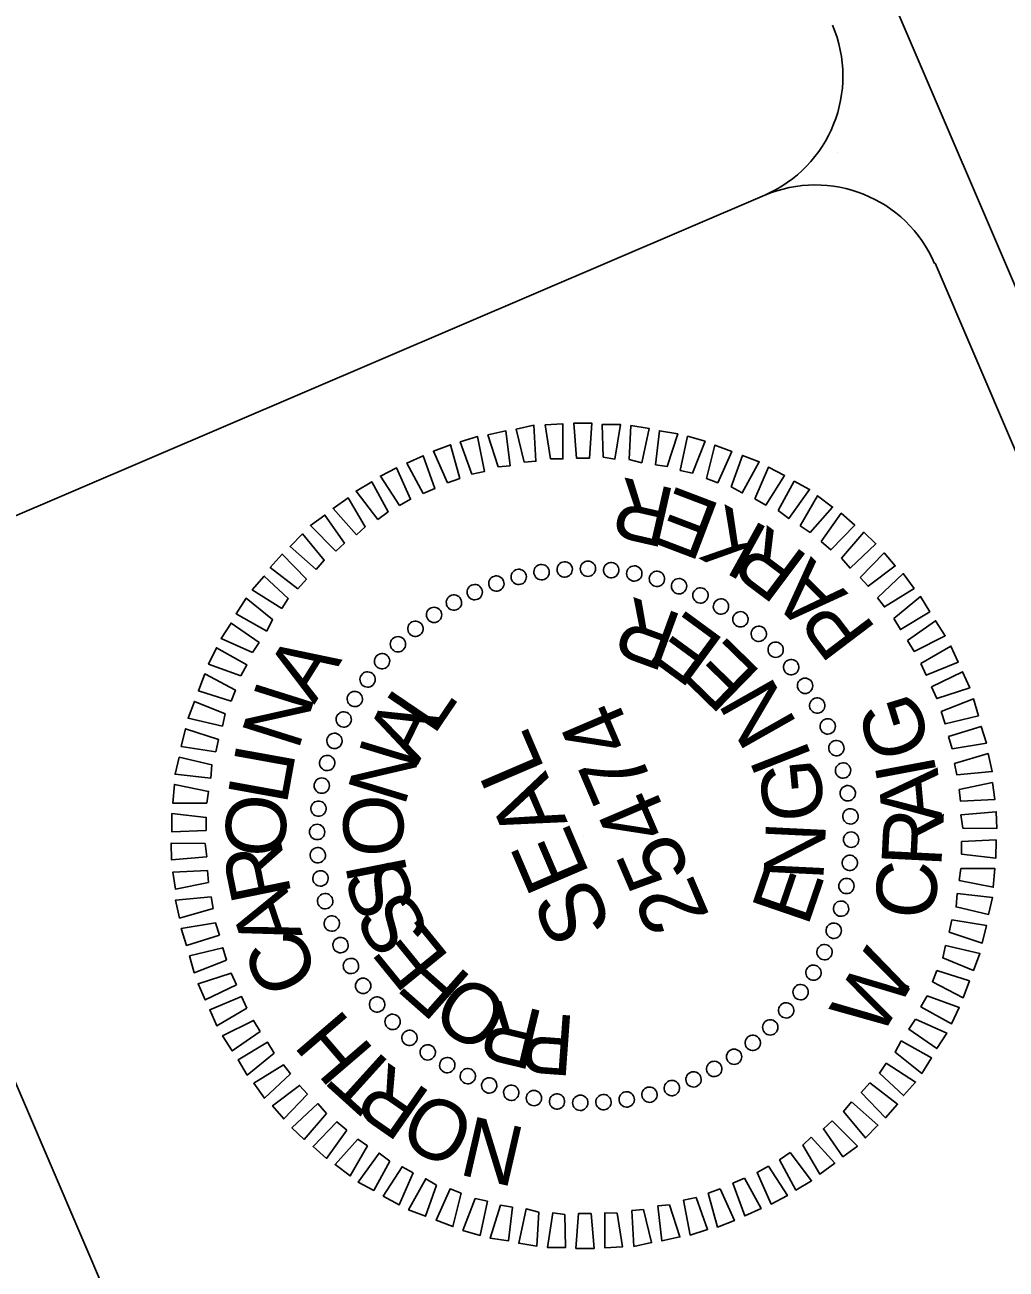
# Model space of a CAD drawing. Extents: x 1550250 to 1553210, y 808906 to 812497.
# Drawn here: x 1552075.2 to 1552205.6, y 811622.3 to 811787.7 of the extents above; entities that cross this region are included whole.
import ezdxf

# ---------------------------------------------------------------- set-up
doc = ezdxf.new("R2010")
doc.units = 0
doc.layers.add('Old_Level_50', color=7, linetype='Continuous')
doc.layers.add('Sheet_Title_CELL', color=7, linetype='Continuous')

msp = doc.modelspace()

# ---------------------------------------------------------------- linework, layer by layer
at = {"layer": 'Old_Level_50'}
for p, q in [((1552183.22, 811770.69), (1552183.22, 811770.69)), ((1552149.96, 811715.41), (1552149.96, 811715.41)), ((1552140.76, 811714.31), (1552140.76, 811714.31)), ((1552143.8, 811714.98), (1552143.8, 811714.98)), ((1552146.89, 811715.35), (1552146.89, 811715.35)), ((1552153.06, 811715.25), (1552153.06, 811715.25)), ((1552156.15, 811714.78), (1552156.15, 811714.78)), ((1552159.16, 811714.11), (1552159.16, 811714.11)), ((1552134.91, 811712.31), (1552134.91, 811712.31)), ((1552137.81, 811713.45), (1552137.81, 811713.45)), ((1552162.1, 811713.1), (1552162.1, 811713.1)), ((1552132.13, 811710.9), (1552132.13, 811710.9)), ((1552164.96, 811711.91), (1552164.96, 811711.91)), ((1552129.53, 811709.27), (1552129.53, 811709.27)), ((1552167.65, 811710.4), (1552167.65, 811710.4)), ((1552127.01, 811707.44), (1552127.01, 811707.44)), ((1552170.27, 811708.71), (1552170.27, 811708.71)), ((1552172.69, 811706.77), (1552172.69, 811706.77)), ((1552124.68, 811705.38), (1552124.68, 811705.38)), ((1552174.95, 811704.68), (1552174.95, 811704.68)), ((1552122.59, 811703.13), (1552122.59, 811703.13)), ((1552177.01, 811702.34), (1552177.01, 811702.34)), ((1552120.65, 811700.71), (1552120.65, 811700.71)), ((1552178.84, 811699.83), (1552178.84, 811699.83)), ((1552118.96, 811698.09), (1552118.96, 811698.09)), ((1552180.47, 811697.23), (1552180.47, 811697.23)), ((1552117.45, 811695.39), (1552117.45, 811695.39)), ((1552181.87, 811694.44), (1552181.87, 811694.44)), ((1552116.25, 811692.53), (1552116.25, 811692.53)), ((1552183.02, 811691.55), (1552183.02, 811691.55)), ((1552115.25, 811689.59), (1552115.25, 811689.59)), ((1552183.88, 811688.6), (1552183.88, 811688.6)), ((1552114.58, 811686.58), (1552114.58, 811686.58)), ((1552184.54, 811685.56), (1552184.54, 811685.56)), ((1552114.1, 811683.49), (1552114.1, 811683.49)), ((1552184.92, 811682.47), (1552184.92, 811682.47)), ((1552113.94, 811680.4), (1552113.94, 811680.4)), ((1552149.46, 811679.9), (1552149.46, 811679.9)), ((1552184.98, 811679.39), (1552184.98, 811679.39)), ((1552114.01, 811677.32), (1552114.01, 811677.32)), ((1552184.82, 811676.3), (1552184.82, 811676.3)), ((1552114.38, 811674.23), (1552114.38, 811674.23)), ((1552184.34, 811673.21), (1552184.34, 811673.21)), ((1552115.05, 811671.2), (1552115.05, 811671.2)), ((1552183.68, 811670.2), (1552183.68, 811670.2)), ((1552115.91, 811668.25), (1552115.91, 811668.25)), ((1552182.67, 811667.26), (1552182.67, 811667.26)), ((1552117.05, 811665.35), (1552117.05, 811665.35)), ((1552181.47, 811664.4), (1552181.47, 811664.4)), ((1552118.46, 811662.57), (1552118.46, 811662.57)), ((1552179.97, 811661.71), (1552179.97, 811661.71)), ((1552120.09, 811659.96), (1552120.09, 811659.96)), ((1552178.27, 811659.09), (1552178.27, 811659.09)), ((1552121.92, 811657.45), (1552121.92, 811657.45)), ((1552176.34, 811656.66), (1552176.34, 811656.66)), ((1552123.97, 811655.11), (1552123.97, 811655.11)), ((1552174.25, 811654.41), (1552174.25, 811654.41)), ((1552126.23, 811653.02), (1552126.23, 811653.02)), ((1552128.65, 811651.08), (1552128.65, 811651.08)), ((1552171.91, 811652.35), (1552171.91, 811652.35)), ((1552131.27, 811649.39), (1552131.27, 811649.39)), ((1552169.4, 811650.52), (1552169.4, 811650.52)), ((1552133.97, 811647.88), (1552133.97, 811647.88)), ((1552166.79, 811648.89), (1552166.79, 811648.89)), ((1552136.83, 811646.69), (1552136.83, 811646.69)), ((1552161.11, 811646.34), (1552161.11, 811646.34)), ((1552164.01, 811647.48), (1552164.01, 811647.48)), ((1552139.77, 811645.68), (1552139.77, 811645.68)), ((1552142.78, 811645.01), (1552142.78, 811645.01)), ((1552145.86, 811644.54), (1552145.86, 811644.54)), ((1552148.96, 811644.38), (1552148.96, 811644.38)), ((1552152.04, 811644.44), (1552152.04, 811644.44)), ((1552155.12, 811644.82), (1552155.12, 811644.82)), ((1552158.16, 811645.48), (1552158.16, 811645.48))]:
    msp.add_line(p, q, dxfattribs=at)
for points in [[(1552138.08, 811728.93), (1552136.71, 811733.2), (1552139.1, 811733.73), (1552139.64, 811729.09)], [(1552141.53, 811729.55), (1552140.48, 811733.96), (1552142.81, 811734.47), (1552143.09, 811729.7)], [(1552145.03, 811730.03), (1552144.33, 811734.53), (1552146.68, 811734.65), (1552146.68, 811730)], [(1552148.49, 811730.11), (1552148.11, 811734.75), (1552150.52, 811734.75), (1552150.2, 811730.1)], [(1552152.01, 811730.22), (1552151.91, 811734.59), (1552154.31, 811734.59), (1552153.58, 811729.99)], [(1552155.48, 811729.91), (1552155.7, 811734.43), (1552158.12, 811734.05), (1552157.14, 811729.5)], [(1552158.97, 811729.23), (1552159.5, 811733.74), (1552161.93, 811733.35), (1552160.54, 811729.01)], [(1552134.55, 811727.97), (1552133.02, 811732.25), (1552135.33, 811732.97), (1552136.25, 811728.34)], [(1552162.26, 811728.46), (1552163.24, 811733.01), (1552165.56, 811732.34), (1552163.89, 811728.11)], [(1552128.11, 811725.39), (1552125.91, 811729.44), (1552128.1, 811730.42), (1552129.66, 811726.08)], [(1552131.34, 811726.84), (1552129.46, 811731.03), (1552131.71, 811731.89), (1552132.95, 811727.4)], [(1552165.76, 811727.39), (1552166.87, 811731.85), (1552169.11, 811730.99), (1552167.26, 811726.83)], [(1552169.04, 811726.31), (1552170.52, 811730.46), (1552172.76, 811729.6), (1552170.5, 811725.49)], [(1552124.94, 811723.81), (1552122.41, 811727.72), (1552124.55, 811728.83), (1552126.43, 811724.63)], [(1552172.18, 811724.69), (1552174, 811728.92), (1552176.14, 811727.78), (1552173.63, 811723.87)], [(1552122.05, 811721.97), (1552119.19, 811725.73), (1552121.27, 811726.97), (1552123.45, 811722.98)], [(1552175.28, 811723.13), (1552177.41, 811727.03), (1552179.45, 811725.94), (1552176.69, 811722.06)], [(1552119.24, 811719.93), (1552116.12, 811723.42), (1552118.11, 811724.85), (1552120.39, 811720.99)], [(1552178.2, 811721.11), (1552180.52, 811725.1), (1552182.52, 811723.59), (1552179.53, 811720.23)], [(1552116.49, 811717.76), (1552113.11, 811721.14), (1552115.04, 811722.54), (1552117.64, 811718.82)], [(1552181, 811719.03), (1552183.66, 811722.78), (1552185.46, 811721.19), (1552182.28, 811717.9)], [(1552113.88, 811715.28), (1552110.4, 811718.37), (1552112.05, 811720.04), (1552114.95, 811716.53)], [(1552183.7, 811716.83), (1552186.66, 811720.25), (1552188.27, 811718.73), (1552184.84, 811715.48)], [(1552111.46, 811712.72), (1552107.78, 811715.56), (1552109.37, 811717.36), (1552112.59, 811714)], [(1552186.18, 811714.22), (1552189.36, 811717.51), (1552190.84, 811715.77), (1552187.24, 811713.07)], [(1552109.29, 811710.11), (1552105.37, 811712.62), (1552106.97, 811714.42), (1552110.17, 811711.44)], [(1552188.48, 811711.53), (1552191.91, 811714.77), (1552193.34, 811712.78), (1552189.41, 811710.32)], [(1552107.3, 811707.12), (1552103.24, 811709.42), (1552104.57, 811711.48), (1552108.09, 811708.64)], [(1552190.64, 811708.78), (1552194.22, 811711.7), (1552195.43, 811709.68), (1552191.53, 811707.31)], [(1552105.4, 811704.26), (1552101.24, 811706.11), (1552102.56, 811708.18), (1552106.28, 811705.58)], [(1552192.49, 811705.88), (1552196.21, 811708.48), (1552197.49, 811706.49), (1552193.38, 811704.42)], [(1552103.85, 811701.15), (1552099.58, 811702.73), (1552100.62, 811704.9), (1552104.67, 811702.61)], [(1552194.26, 811702.8), (1552198.25, 811705.13), (1552199.21, 811703), (1552194.96, 811701.25)], [(1552102.57, 811697.79), (1552098.22, 811699.17), (1552099.08, 811701.42), (1552103.14, 811699.28)], [(1552195.65, 811699.7), (1552199.79, 811701.71), (1552200.74, 811699.58), (1552196.35, 811698.15)], [(1552101.42, 811694.48), (1552096.84, 811695.52), (1552097.69, 811697.77), (1552101.77, 811696.11)], [(1552196.97, 811696.41), (1552201.25, 811698.1), (1552201.89, 811695.83), (1552197.47, 811694.77)], [(1552100.55, 811691.06), (1552095.95, 811691.79), (1552096.52, 811694.14), (1552100.9, 811692.69)], [(1552197.91, 811693.11), (1552202.27, 811694.45), (1552202.97, 811692.2), (1552198.41, 811691.47)], [(1552198.74, 811689.53), (1552203.2, 811690.83), (1552203.73, 811688.43), (1552199.03, 811688.03)], [(1552099.86, 811687.57), (1552095.13, 811688.09), (1552095.67, 811690.35), (1552100, 811689.34)], [(1552099.34, 811684.24), (1552094.84, 811684.24), (1552095.04, 811686.73), (1552099.57, 811685.81)], [(1552199.36, 811686.08), (1552203.77, 811686.97), (1552204.08, 811684.71), (1552199.51, 811684.52)], [(1552099.25, 811680.63), (1552094.69, 811680.44), (1552094.69, 811682.85), (1552099.26, 811682.34)], [(1552199.56, 811682.68), (1552204.27, 811683.09), (1552204.34, 811680.87), (1552199.81, 811680.93)], [(1552199.67, 811679.16), (1552204.24, 811679.35), (1552204.23, 811676.94), (1552199.66, 811677.45)], [(1552099.36, 811677.11), (1552094.66, 811676.7), (1552094.59, 811678.92), (1552099.12, 811678.86)], [(1552099.57, 811673.71), (1552095.16, 811672.82), (1552094.84, 811675.08), (1552099.41, 811675.27)], [(1552199.58, 811675.55), (1552204.08, 811675.56), (1552203.88, 811673.06), (1552199.36, 811673.98)], [(1552100.18, 811670.26), (1552095.73, 811668.96), (1552095.19, 811671.36), (1552099.9, 811671.77)], [(1552199.06, 811672.22), (1552203.79, 811671.7), (1552203.26, 811669.45), (1552198.93, 811670.45)], [(1552101.02, 811666.68), (1552096.65, 811665.34), (1552095.95, 811667.59), (1552100.51, 811668.32)], [(1552198.38, 811668.73), (1552202.97, 811668), (1552202.4, 811665.65), (1552198.03, 811667.1)], [(1552101.96, 811663.38), (1552097.67, 811661.69), (1552097.04, 811663.97), (1552101.45, 811665.02)], [(1552197.51, 811665.31), (1552202.09, 811664.27), (1552201.23, 811662.02), (1552197.16, 811663.68)], [(1552103.28, 811660.09), (1552099.14, 811658.08), (1552098.18, 811660.21), (1552102.58, 811661.64)], [(1552196.36, 811662), (1552200.7, 811660.62), (1552199.85, 811658.37), (1552195.79, 811660.51)], [(1552104.67, 811657), (1552100.67, 811654.66), (1552099.72, 811656.79), (1552103.97, 811658.54)], [(1552195.07, 811658.64), (1552199.35, 811657.06), (1552198.31, 811654.89), (1552194.25, 811657.18)], [(1552106.44, 811653.91), (1552102.72, 811651.31), (1552101.44, 811653.3), (1552105.55, 811655.37)], [(1552193.52, 811655.53), (1552197.69, 811653.68), (1552196.37, 811651.61), (1552192.64, 811654.21)], [(1552191.63, 811652.67), (1552195.68, 811650.38), (1552194.36, 811648.31), (1552190.83, 811651.15)], [(1552108.28, 811651.02), (1552104.71, 811648.09), (1552103.49, 811650.11), (1552107.39, 811652.48)], [(1552110.45, 811648.27), (1552107.02, 811645.02), (1552105.58, 811647.01), (1552109.52, 811649.48)], [(1552189.63, 811649.68), (1552193.55, 811647.17), (1552191.95, 811645.37), (1552188.75, 811648.35)], [(1552112.74, 811645.57), (1552109.56, 811642.28), (1552108.08, 811644.02), (1552111.68, 811646.72)], [(1552187.47, 811647.08), (1552191.15, 811644.23), (1552189.55, 811642.43), (1552186.33, 811645.79)], [(1552115.23, 811642.97), (1552112.27, 811639.54), (1552110.65, 811641.07), (1552114.08, 811644.31)], [(1552185.05, 811644.52), (1552188.53, 811641.43), (1552186.87, 811639.75), (1552183.98, 811643.26)], [(1552117.93, 811640.76), (1552115.27, 811637.01), (1552113.47, 811638.6), (1552116.64, 811641.89)], [(1552182.44, 811642.03), (1552185.81, 811638.66), (1552183.89, 811637.25), (1552181.29, 811640.97)], [(1552120.72, 811638.68), (1552118.4, 811634.69), (1552116.4, 811636.2), (1552119.4, 811639.56)], [(1552179.69, 811639.86), (1552182.8, 811636.37), (1552180.81, 811634.94), (1552178.54, 811638.8)], [(1552123.65, 811636.66), (1552121.52, 811632.76), (1552119.47, 811633.86), (1552122.23, 811637.73)], [(1552176.88, 811637.82), (1552179.73, 811634.06), (1552177.65, 811632.82), (1552175.47, 811636.81)], [(1552126.75, 811635.1), (1552124.92, 811630.87), (1552122.79, 811632.01), (1552125.3, 811635.92)], [(1552170.81, 811634.4), (1552173.02, 811630.35), (1552170.83, 811629.37), (1552169.26, 811633.71)], [(1552173.98, 811635.98), (1552176.51, 811632.08), (1552174.37, 811630.96), (1552172.49, 811635.16)], [(1552129.88, 811633.48), (1552128.41, 811629.33), (1552126.16, 811630.19), (1552128.43, 811634.31)], [(1552133.16, 811632.4), (1552132.06, 811627.95), (1552129.81, 811628.8), (1552131.67, 811632.97)], [(1552167.59, 811632.96), (1552169.47, 811628.76), (1552167.22, 811627.9), (1552165.98, 811632.39)], [(1552136.66, 811631.33), (1552135.68, 811626.78), (1552133.37, 811627.45), (1552135.03, 811631.69)], [(1552164.37, 811631.82), (1552165.9, 811627.55), (1552163.59, 811626.82), (1552162.68, 811631.45)], [(1552139.96, 811630.56), (1552139.42, 811626.05), (1552137, 811626.44), (1552138.38, 811630.79)], [(1552143.45, 811629.88), (1552143.22, 811625.36), (1552140.8, 811625.74), (1552141.78, 811630.3)], [(1552146.92, 811629.57), (1552147.02, 811625.2), (1552144.61, 811625.2), (1552145.34, 811629.8)], [(1552150.44, 811629.68), (1552150.81, 811625.04), (1552148.41, 811625.05), (1552148.73, 811629.69)], [(1552153.89, 811629.76), (1552154.59, 811625.26), (1552152.24, 811625.14), (1552152.25, 811629.8)], [(1552157.4, 811630.24), (1552158.45, 811625.83), (1552156.12, 811625.33), (1552155.84, 811630.09)], [(1552160.84, 811630.86), (1552162.22, 811626.59), (1552159.82, 811626.06), (1552159.29, 811630.7)]]:
    msp.add_lwpolyline(points, close=True, dxfattribs=at)
for centre, major_axis in [((1552140.8, 811714.32), (-0.25, 0.988)), ((1552143.83, 811714.95), (-0.16, 1.01)), ((1552146.91, 811715.31), (-0.07, 1.02)), ((1552150, 811715.4), (0.01, 1.02)), ((1552153.09, 811715.22), (0.1, 1.01)), ((1552156.16, 811714.77), (0.19, 1)), ((1552137.83, 811713.43), (-0.335, 0.963)), ((1552159.17, 811714.05), (0.278, 0.98)), ((1552162.11, 811713.08), (0.362, 0.952)), ((1552134.95, 811712.29), (-0.417, 0.93)), ((1552164.95, 811711.85), (0.444, 0.917)), ((1552129.55, 811709.27), (-0.572, 0.843)), ((1552132.19, 811710.9), (-0.497, 0.89)), ((1552167.68, 811710.38), (0.522, 0.875)), ((1552170.27, 811708.68), (0.596, 0.826)), ((1552127.07, 811707.42), (-0.644, 0.79)), ((1552172.7, 811706.76), (0.666, 0.771)), ((1552124.75, 811705.36), (-0.71, 0.731)), ((1552174.95, 811704.64), (0.731, 0.71)), ((1552122.63, 811703.11), (-0.771, 0.666)), ((1552177.01, 811702.32), (0.79, 0.644)), ((1552120.71, 811700.68), (-0.826, 0.596)), ((1552178.86, 811699.84), (0.843, 0.572)), ((1552119.01, 811698.09), (-0.875, 0.522)), ((1552180.48, 811697.21), (0.89, 0.497)), ((1552117.54, 811695.37), (-0.917, 0.444)), ((1552181.87, 811694.44), (0.93, 0.417)), ((1552116.31, 811692.52), (-0.952, 0.362)), ((1552183.02, 811691.56), (0.963, 0.335)), ((1552115.34, 811689.58), (-0.98, 0.278)), ((1552183.91, 811688.59), (0.988, 0.25)), ((1552114.62, 811686.57), (-1, 0.19)), ((1552184.53, 811685.56), (1.01, 0.16)), ((1552114.18, 811683.51), (-1.01, 0.1)), ((1552184.89, 811682.49), (1.02, 0.07)), ((1552114, 811680.41), (-1.02, 0.01)), ((1552184.98, 811679.39), (1.02, -0.01)), ((1552114.09, 811677.32), (-1.02, -0.07)), ((1552184.8, 811676.3), (1.01, -0.1)), ((1552114.45, 811674.24), (-1.01, -0.16)), ((1552184.36, 811673.23), (1, -0.19)), ((1552115.07, 811671.21), (-0.988, -0.25)), ((1552183.64, 811670.22), (0.98, -0.278)), ((1552115.96, 811668.24), (-0.963, -0.335)), ((1552182.67, 811667.28), (0.952, -0.362)), ((1552117.11, 811665.37), (-0.93, -0.417)), ((1552181.44, 811664.44), (0.917, -0.444)), ((1552118.5, 811662.6), (-0.89, -0.497)), ((1552179.97, 811661.71), (0.875, -0.522)), ((1552120.12, 811659.96), (-0.843, -0.572)), ((1552178.27, 811659.12), (0.826, -0.596)), ((1552121.97, 811657.48), (-0.79, -0.644)), ((1552176.35, 811656.7), (0.771, -0.666)), ((1552124.03, 811655.17), (-0.731, -0.71)), ((1552126.28, 811653.04), (-0.666, -0.771)), ((1552174.23, 811654.44), (0.71, -0.731)), ((1552171.91, 811652.38), (0.644, -0.79)), ((1552128.71, 811651.12), (-0.596, -0.826)), ((1552169.43, 811650.53), (0.572, -0.843)), ((1552131.3, 811649.42), (-0.522, -0.875)), ((1552166.79, 811648.91), (0.497, -0.89)), ((1552134.03, 811647.95), (-0.444, -0.917)), ((1552136.87, 811646.72), (-0.362, -0.952)), ((1552164.03, 811647.52), (0.417, -0.93)), ((1552139.81, 811645.75), (-0.278, -0.98)), ((1552142.82, 811645.04), (-0.19, -1)), ((1552155.15, 811644.86), (0.16, -1.01)), ((1552158.18, 811645.49), (0.25, -0.988)), ((1552161.15, 811646.37), (0.335, -0.963)), ((1552145.89, 811644.59), (-0.1, -1.01)), ((1552148.98, 811644.41), (-0.01, -1.02)), ((1552152.07, 811644.5), (0.07, -1.02))]:
    msp.add_ellipse(centre, major_axis=major_axis, ratio=0.999708, dxfattribs=at)
at = {"layer": 'Sheet_Title_CELL'}
for p, q in [((1553086.33, 809698.16), (1551983.97, 812273.45)), ((1552173.52, 811765.06), (1551919.79, 811656.45)), ((1552195.84, 811362.24), (1552046.65, 811710.76))]:
    msp.add_line(p, q, dxfattribs=at)
msp.add_lwpolyline([(1552331.77, 811439.19), (1552196.16, 811756)], dxfattribs=at)
for centre, start, end in [((1552166.64, 811780.89), 293.1736, 23.1736), ((1552180.22, 811749.17), 23.1736, 113.1736)]:
    msp.add_arc(centre, 17.25, start, end, dxfattribs=at)

# ---------------------------------------------------------------- texts
at = {"layer": 'Old_Level_50'}
for s, height, rotation, p in [('R', 7.98, 167.1736, (1552161.9, 811725.93)), ('E', 7.98, 159.1736, (1552167.91, 811723.86)), ('K', 7.98, 151.1736, (1552174.28, 811720.63)), ('R', 7.98, 143.1736, (1552179.55, 811716.89)), ('A', 7.98, 135.1736, (1552184.66, 811712.1)), ('R', 7.98, 159.9007, (1552162.81, 811709.17)), ('E', 7.98, 143.75, (1552168.36, 811705.81)), ('P', 7.98, 127.1736, (1552188.46, 811707.34)), ('E', 7.98, 135.6747, (1552173.22, 811701.52)), ('A', 7.98, 57.9454, (1552113.62, 811697.29)), ('N', 7.98, 119.524, (1552177.93, 811694.71)), ('N', 7.98, 72.4818, (1552111.47, 811691.1)), ('L', 7.98, 55.9201, (1552129.49, 811693.1)), ('25474', 8.492, 113.1736, (1552166.24, 811669.22)), ('G', 7.98, 107.1736, (1552195.74, 811691.54)), ('A', 7.98, 63.7515, (1552127.4, 811689.28)), ('SEAL', 8.49, 113.1736, (1552153.3, 811667.79)), ('N', 7.98, 73.0954, (1552125.58, 811683.62)), ('I', 7.98, 79.7499, (1552110.7, 811688.13)), ('I', 7.98, 111.4487, (1552179.85, 811690.27)), ('L', 7.98, 79.7499, (1552109.93, 811683.88)), ('G', 7.98, 95.298, (1552181.47, 811682.16)), ('I', 7.98, 100.6736, (1552196.41, 811688.06)), ('A', 7.98, 95.1736, (1552197.12, 811681.94)), ('O', 7.98, 87.0181, (1552109.65, 811676.93)), ('O', 7.98, 91.7832, (1552125.6, 811677.23)), ('R', 7.98, 87.1736, (1552196.96, 811675.64)), ('N', 7.98, 87.2227, (1552181.28, 811673.86)), ('R', 7.98, 101.5544, (1552110.64, 811672.07)), ('I', 7.98, 101.1271, (1552126.07, 811674.79)), ('S', 7.98, 110.4711, (1552127.33, 811670.75)), ('E', 7.98, 71.0721, (1552179.18, 811667.67)), ('C', 7.98, 87.1736, (1552196.16, 811668.74)), ('A', 7.98, 108.8226, (1552112.12, 811666.69)), ('S', 7.98, 119.815, (1552129.27, 811666.98)), ('E', 7.98, 129.1589, (1552131.78, 811663.7)), ('C', 7.98, 116.0907, (1552114.5, 811661.23)), ('W', 7.98, 59.1728, (1552188.77, 811652.78)), ('F', 7.98, 138.5028, (1552134.78, 811660.92)), ('O', 7.98, 147.8467, (1552140.13, 811657.49)), ('.', 7.98, 63.6735, (1552191.85, 811658.12)), ('R', 7.98, 166.5346, (1552144.4, 811656.49)), ('H', 7.98, 130.6271, (1552121.78, 811651.33)), ('P', 7.98, 175.8785, (1552148.5, 811655.96)), ('T', 7.98, 137.8952, (1552125.28, 811648.36)), ('R', 7.98, 145.1634, (1552129.37, 811645.62)), ('O', 7.98, 152.4315, (1552135.57, 811642.47)), ('N', 7.98, 166.9679, (1552141.97, 811640.97))]:
    msp.add_text(s, height=height, rotation=rotation, dxfattribs=at).set_placement(p)

doc.saveas('drawing.dxf')
